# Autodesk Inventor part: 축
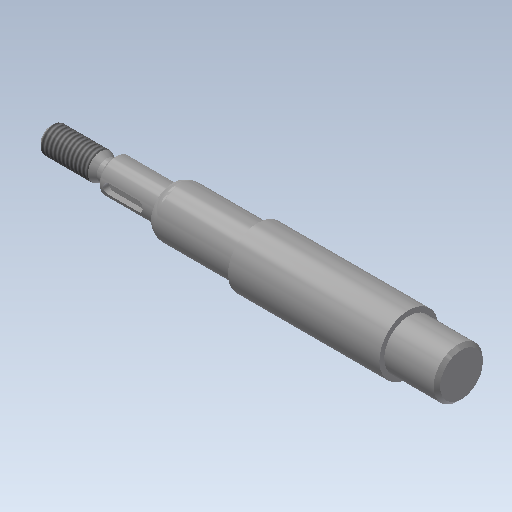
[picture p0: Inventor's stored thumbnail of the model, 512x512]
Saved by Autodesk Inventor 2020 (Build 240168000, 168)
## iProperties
Created: 2015-11
Part Number: 축
Material: 강철, 연강
Document SubType Name: Modeling
Designer: mduedu
Density: 1 g/cm^3
Appearance: 강철
Author: mduedu
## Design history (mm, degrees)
sketch "스케치1"
  geometry: L1 (-86, 0)-(86, 0); L2 (-86, 0)-(-86, 4); L3 (-86, 4)-(-70.732, 4); L4 (-70.732, 4)-(-69, 3); L5 (-69, 3)-(-67, 3); L6 (-67, 3)-(-67, 5); L7 (-67, 5)-(-49, 5); L8 (-49, 5)-(-49, 6.55); L9 (-47.355, 7.5)-(-23, 7.5); L10 (-23, 7.5)-(-23, 9); L11 (0, 0)-(0, 9); L12 (86, 4)-(70.732, 4); L13 (70.732, 4)-(69, 3); L14 (69, 3)-(67, 3); L15 (67, 3)-(67, 5); L16 (67, 5)-(49, 5); L17 (23, 7.5)-(23, 9); L18 (86, 0)-(86, 4); L19 (-23, 9)-(23, 9); L20 (-49, 6.55)-(-47.355, 7.5); L21 (47.355, 7.5)-(23, 7.5); L22 (49, 6.55)-(47.355, 7.5); L23 (49, 5)-(49, 6.55); 1 further point
  constraints: 46 end point, 10 symmetric about line, 6 perpendicular, 5 parallel, 2 midpoint, 1 coincident, 1 horizontal
  dimensions: "d0" = 172 distance of L1.start L1.end (derived); "d1" = 8 diameter of L3 L1; "d2" = 30 deg angle of L4 L5; "d3" = 6 diameter of L5 L1; "d4" = 10 diameter of L7 L1; "d5" = 15 diameter of L9 L1; "d6" = 18 diameter of L19 L1; "d8" = 18 distance of L6.end L7.end; "d9" = 46 distance of L10.end L17.end; "d10" = 2 distance of L4.end L5.end; "d11" = 17 distance from line of L4.end L2; "d16" = 13.1 diameter of L8.end L1; "d17" = 30 deg angle of L20 L9; "d18" = 26 distance between parallel lines of L10 L8
revolve "회전1" sketch "스케치1" stored, may be unused: angle "d12" = 90 deg
chamfer "모따기1" distance "d13" = 1; stored, may be unused: second distance "d14" = 2, angle "d15" = 45 deg
fillet "모깎기1" dims "d19" = 4, "d20" = 0.5
node "작업 평면1"
sketch "스케치2" dims "d23" = 12
  geometry: L1 (-5.5, 1.5)-(3.5, 1.5); L2 (3.5, 1.5)-(3.5, -1.5); L3 (3.5, -1.5)-(-5.5, -1.5); L4 (-5.5, -1.5)-(-5.5, 1.5); L5 (-9, -4)-(-9, 4) reference; 3 further points
  constraints: 8 end point, 2 midpoint, 2 parallel, 2 vertical alignment, 1 horizontal, 1 perpendicular, 4 other
  dimensions: "d21" = 3 distance between parallel lines of L3 L1; "d24" = 2 dimension on L5
extrude "돌출1" cut sketch "스케치2" distance "d25" = 1.8; taper "d26" = 0 deg
feature "스레드1" dims "d27" = 10, "d28" = 0
feature "스레드2" dims "d29" = 10, "d30" = 0
chamfer "모따기2" distance "d31" = 1; stored, may be unused: second distance "d32" = 2, angle "d33" = 45 deg
node "작업 평면2"
sketch "스케치3"
  geometry: C1 r 7.5 at (0, 0) reference; 1 further point
extrude "돌출2" cut sketch "스케치3" extent not by distance; stored distance "d36" = 10; taper "d37" = 0 deg
chamfer "모따기3" distance "d38" = 1; stored, may be unused: second distance "d39" = 2, angle "d40" = 45 deg
node "솔리드1"
mirror "대칭1"
node "절단 모서리 투영1"
other parameters: "d35" = 16
